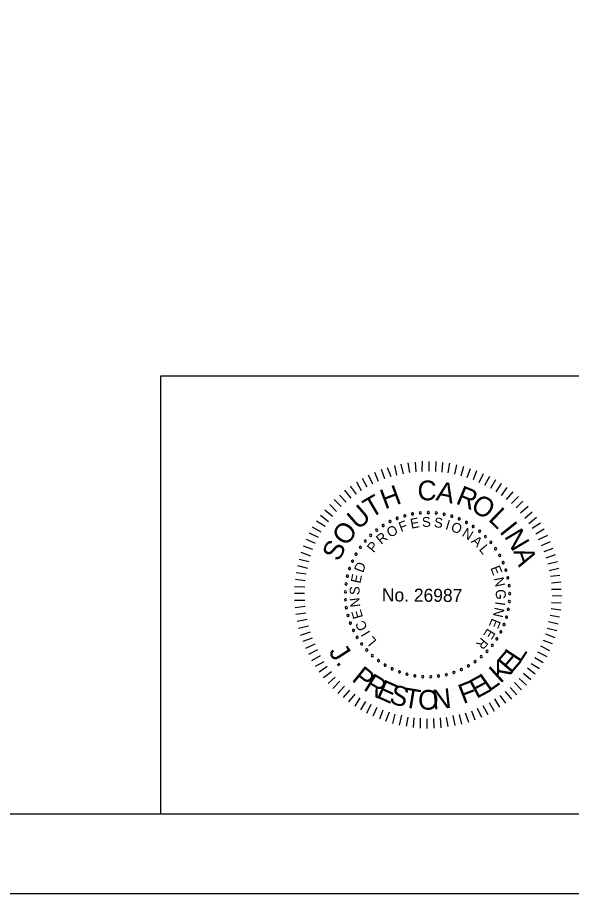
# Model space of a CAD drawing. Extents: x -125.5 to -89.4, y -5.1 to 16.9.
# Drawn here: x -103.8 to -100.32, y -5.07 to 0.43 of the extents above; entities that cross this region are included whole.
import ezdxf

# ---------------------------------------------------------------- set-up
doc = ezdxf.new("R2010")
doc.units = 0
for name, color, linetype in [('BR_BORDER LINES', 7, 'Continuous'), ('BR_TEXT', 7, 'Continuous'), ('Level 31', 7, 'Continuous')]:
    doc.layers.add(name, color=color, linetype=linetype)

msp = doc.modelspace()

# ---------------------------------------------------------------- linework, layer by layer
at = {"layer": 'BR_BORDER LINES'}
for p, q in [((-102.8989, -1.8161), (-97.5337, -1.8161)), ((-102.8989, -4.5661), (-102.8989, -1.8161)), ((-123.6994, -4.5662), (-90.0334, -4.5662))]:
    msp.add_line(p, q, dxfattribs=at)
at = {"layer": 'BR_TEXT'}
for p, q in [((-101.3372, -2.423), (-101.3461, -2.362)), ((-101.2977, -2.419), (-101.3015, -2.3581)), ((-101.2582, -2.4168), (-101.2576, -2.3524)), ((-101.2161, -2.4146), (-101.2156, -2.3528)), ((-101.1741, -2.4175), (-101.1718, -2.3531)), ((-101.1338, -2.4204), (-101.129, -2.3595)), ((-101.0952, -2.425), (-101.0844, -2.3642)), ((-101.4937, -2.4629), (-101.5147, -2.4044)), ((-101.4541, -2.4504), (-101.476, -2.3927)), ((-101.418, -2.4404), (-101.4312, -2.3793)), ((-101.3767, -2.4304), (-101.3908, -2.3711)), ((-101.0549, -2.4331), (-101.0407, -2.374)), ((-101.0138, -2.4437), (-100.9979, -2.3829)), ((-100.977, -2.4543), (-100.9551, -2.397)), ((-100.9376, -2.4675), (-100.9157, -2.4093)), ((-101.604, -2.5144), (-101.6344, -2.46)), ((-101.5695, -2.4966), (-101.5957, -2.4406)), ((-101.5325, -2.4798), (-101.556, -2.4238)), ((-100.9017, -2.485), (-100.8738, -2.4294)), ((-100.8658, -2.5024), (-100.8345, -2.4469)), ((-100.8282, -2.5208), (-100.796, -2.467)), ((-101.6704, -2.5593), (-101.7095, -2.5083)), ((-101.6394, -2.5381), (-101.6698, -2.4838)), ((-100.795, -2.5451), (-100.761, -2.4913)), ((-100.7617, -2.5668), (-100.7252, -2.5165)), ((-101.7369, -2.6094), (-101.7786, -2.5644)), ((-101.7041, -2.5847), (-101.744, -2.5346)), ((-100.7293, -2.5928), (-100.6886, -2.5434)), ((-100.6977, -2.618), (-100.6545, -2.5737)), ((-101.7958, -2.6673), (-101.8392, -2.6248)), ((-101.7663, -2.6366), (-101.8106, -2.5925)), ((-100.6697, -2.6456), (-100.6264, -2.6022)), ((-100.6416, -2.6768), (-100.594, -2.6351)), ((-101.8469, -2.732), (-101.8964, -2.6922)), ((-101.8209, -2.6988), (-101.8704, -2.6598)), ((-100.6144, -2.7088), (-100.5677, -2.6705)), ((-101.8686, -2.761), (-101.9224, -2.728)), ((-100.5906, -2.7424), (-100.5414, -2.7033)), ((-100.5686, -2.7718), (-100.516, -2.7396)), ((-101.9104, -2.8319), (-101.9668, -2.804)), ((-101.893, -2.7977), (-101.9467, -2.7656)), ((-100.5466, -2.8089), (-100.4931, -2.7776)), ((-101.9279, -2.8687), (-101.9852, -2.8433)), ((-100.5288, -2.8433), (-100.4711, -2.8164)), ((-100.5111, -2.8804), (-100.4543, -2.856)), ((-101.9454, -2.9072), (-102.0035, -2.8852)), ((-100.4943, -2.9192), (-100.4374, -2.8982)), ((-101.97, -2.9833), (-102.0308, -2.9682)), ((-101.9577, -2.9474), (-102.0193, -2.9246)), ((-100.4809, -2.9596), (-100.4232, -2.9378)), ((-101.9772, -3.0253), (-102.0397, -3.0094)), ((-100.4708, -2.9957), (-100.4107, -2.9816)), ((-100.4626, -3.0378), (-100.4024, -3.0229)), ((-101.9878, -3.0613), (-102.0487, -3.0531)), ((-100.4543, -3.074), (-100.3951, -3.0667)), ((-101.9925, -3.1024), (-102.0542, -3.0951)), ((-100.4478, -3.1152), (-100.3868, -3.1088)), ((-101.9974, -3.183), (-102.06, -3.1825)), ((-101.9954, -3.1419), (-102.0597, -3.1414)), ((-100.4464, -3.1547), (-100.3863, -3.1552)), ((-101.9961, -3.226), (-102.0604, -3.2272)), ((-100.4471, -3.2388), (-100.3871, -3.241)), ((-100.4442, -3.1959), (-100.3833, -3.1964)), ((-101.9938, -3.2646), (-102.0556, -3.2718)), ((-100.4492, -3.2774), (-100.3883, -3.2856)), ((-101.9898, -3.3058), (-102.0509, -3.3148)), ((-101.9799, -3.3454), (-102.0426, -3.3586)), ((-100.4564, -3.3185), (-100.3972, -3.3284)), ((-101.9733, -3.3875), (-102.0344, -3.4016)), ((-100.4742, -3.3999), (-100.4143, -3.415)), ((-100.4653, -3.3579), (-100.4053, -3.3721)), ((-101.9616, -3.4245), (-102.0236, -3.4454)), ((-101.95, -3.4632), (-102.0085, -3.4842)), ((-100.4848, -3.4367), (-100.4275, -3.4586)), ((-101.9331, -3.5003), (-101.9908, -3.5272)), ((-100.5163, -3.512), (-100.4599, -3.5399)), ((-100.4989, -3.4752), (-100.4424, -3.4971)), ((-101.9162, -3.5364), (-101.9731, -3.566)), ((-101.8994, -3.5735), (-101.9537, -3.6048)), ((-100.5346, -3.5479), (-100.4774, -3.5784)), ((-101.8756, -3.6106), (-101.93, -3.6419)), ((-100.5756, -3.6213), (-100.5235, -3.6535)), ((-100.553, -3.5846), (-100.5, -3.6168)), ((-101.8544, -3.6399), (-101.9045, -3.6764)), ((-101.829, -3.6736), (-101.8791, -3.7127)), ((-100.6224, -3.6836), (-100.5764, -3.7234)), ((-100.5981, -3.6503), (-100.5495, -3.6876)), ((-101.8043, -3.7073), (-101.8485, -3.7481)), ((-101.7754, -3.7333), (-101.8204, -3.7784)), ((-100.6502, -3.7168), (-100.6033, -3.7584)), ((-101.7465, -3.7636), (-101.7889, -3.8095)), ((-101.714, -3.7895), (-101.7548, -3.8364)), ((-100.7073, -3.7721), (-100.6648, -3.8188)), ((-100.6787, -3.7423), (-100.6362, -3.7882)), ((-101.6808, -3.8156), (-101.7207, -3.8633)), ((-101.6501, -3.8373), (-101.6814, -3.8894)), ((-100.8057, -3.8443), (-100.7727, -3.8969)), ((-100.772, -3.8231), (-100.7364, -3.8714)), ((-100.7392, -3.7976), (-100.6993, -3.8452)), ((-101.6151, -3.8599), (-101.6464, -3.9137)), ((-101.5809, -3.8799), (-101.608, -3.9355)), ((-101.5442, -3.8974), (-101.5687, -3.953)), ((-100.9135, -3.9026), (-100.8865, -3.9586)), ((-100.8773, -3.8857), (-100.8468, -3.9418)), ((-100.8393, -3.8663), (-100.808, -3.9206)), ((-101.5057, -3.9149), (-101.5276, -3.9713)), ((-101.4663, -3.9272), (-101.4891, -3.9854)), ((-101.4304, -3.9395), (-101.4446, -3.9986)), ((-101.3892, -3.9467), (-101.4044, -4.0084)), ((-101.3499, -3.9582), (-101.3598, -4.0165)), ((-101.0675, -3.9494), (-101.0542, -4.0113)), ((-101.0262, -3.9429), (-101.0112, -4.0022)), ((-100.9892, -3.9311), (-100.9682, -3.9897)), ((-100.9496, -3.9194), (-100.9286, -3.9763)), ((-101.3104, -3.9628), (-101.3152, -4.0246)), ((-101.271, -3.9657), (-101.2715, -4.0275)), ((-101.229, -3.9686), (-101.2295, -4.0296)), ((-101.1869, -3.9664), (-101.1857, -4.0282)), ((-101.1466, -3.9642), (-101.1428, -4.026)), ((-101.1079, -3.9602), (-101.098, -4.0186))]:
    msp.add_line(p, q, dxfattribs=at)
for centre, start, end in [((-101.3681, -2.6945), 16.1422, 196.1422), ((-101.3681, -2.6945), 196.1422, 16.1422), ((-101.3196, -2.6831), 10.6038, 190.6038), ((-101.3196, -2.6831), 190.6038, 10.6038), ((-101.2702, -2.6764), 5.0653, 185.0653), ((-101.2702, -2.6764), 185.0653, 5.0653), ((-101.2204, -2.6745), 359.5268, 179.5268), ((-101.2204, -2.6745), 179.5268, 359.5268), ((-101.1707, -2.6774), 173.9884, 353.9884), ((-101.1707, -2.6774), 353.9884, 173.9884), ((-101.1214, -2.6851), 168.4499, 348.4499), ((-101.1214, -2.6851), 348.4499, 168.4499), ((-101.0732, -2.6976), 342.9114, 162.9114), ((-101.5039, -2.7559), 32.7576, 212.7576), ((-101.4607, -2.7311), 27.2191, 207.2191), ((-101.4607, -2.7311), 207.2191, 27.2191), ((-101.4153, -2.7106), 21.6807, 201.6807), ((-101.4153, -2.7106), 201.6807, 21.6807), ((-101.0732, -2.6976), 162.9114, 342.9114), ((-101.0263, -2.7146), 157.373, 337.373), ((-101.0263, -2.7146), 337.373, 157.373), ((-100.9814, -2.736), 151.8345, 331.8345), ((-100.9814, -2.736), 331.8345, 151.8345), ((-101.5445, -2.7848), 38.2961, 218.2961), ((-101.5445, -2.7848), 218.2961, 38.2961), ((-101.5039, -2.7559), 212.7576, 32.7576), ((-100.9387, -2.7617), 146.2961, 326.2961), ((-100.9387, -2.7617), 326.2961, 146.2961), ((-100.8987, -2.7914), 140.7576, 320.7576), ((-100.8987, -2.7914), 320.7576, 140.7576), ((-101.6164, -2.8536), 49.373, 229.373), ((-101.6164, -2.8536), 229.373, 49.373), ((-101.5821, -2.8175), 43.8345, 223.8345), ((-101.5821, -2.8175), 223.8345, 43.8345), ((-100.8617, -2.8249), 135.2191, 315.2191), ((-100.8617, -2.8249), 315.2191, 135.2191), ((-100.8282, -2.8617), 129.6807, 309.6807), ((-100.8282, -2.8617), 309.6807, 129.6807), ((-101.6471, -2.8929), 54.9114, 234.9114), ((-101.6471, -2.8929), 234.9114, 54.9114), ((-100.7983, -2.9016), 124.1422, 304.1422), ((-100.7983, -2.9016), 304.1422, 124.1422), ((-101.6738, -2.935), 60.4499, 240.4499), ((-101.6738, -2.935), 240.4499, 60.4499), ((-100.7724, -2.9442), 118.6038, 298.6038), ((-100.7724, -2.9442), 298.6038, 118.6038), ((-101.7145, -3.0258), 71.5268, 251.5268), ((-101.7145, -3.0258), 251.5268, 71.5268), ((-101.6964, -2.9794), 65.9884, 245.9884), ((-101.6964, -2.9794), 245.9884, 65.9884), ((-100.7508, -2.9891), 113.0653, 293.0653), ((-100.7508, -2.9891), 293.0653, 113.0653), ((-101.7281, -3.0738), 77.0653, 257.0653), ((-101.7281, -3.0738), 257.0653, 77.0653), ((-100.7336, -3.0359), 107.5268, 287.5268), ((-100.7336, -3.0359), 287.5268, 107.5268), ((-100.721, -3.0841), 101.9884, 281.9884), ((-100.721, -3.0841), 281.9884, 101.9884), ((-101.737, -3.1228), 82.6038, 262.6038), ((-101.737, -3.1228), 262.6038, 82.6038), ((-100.7131, -3.1333), 96.4499, 276.4499), ((-100.7131, -3.1333), 276.4499, 96.4499), ((-101.7411, -3.1724), 88.1422, 268.1422), ((-101.7411, -3.1724), 268.1422, 88.1422), ((-100.71, -3.183), 90.9114, 270.9114), ((-100.71, -3.183), 270.9114, 90.9114), ((-101.7404, -3.2223), 93.6807, 273.6807), ((-101.7404, -3.2223), 273.6807, 93.6807), ((-100.7118, -3.2328), 85.373, 265.373), ((-100.7118, -3.2328), 265.373, 85.373), ((-101.7349, -3.2718), 99.2191, 279.2191), ((-101.7349, -3.2718), 279.2191, 99.2191), ((-100.7183, -3.2822), 79.8345, 259.8345), ((-100.7183, -3.2822), 259.8345, 79.8345), ((-101.7246, -3.3206), 104.7576, 284.7576), ((-101.7246, -3.3206), 284.7576, 104.7576), ((-100.7295, -3.3308), 74.2961, 254.2961), ((-100.7295, -3.3308), 254.2961, 74.2961), ((-101.7097, -3.3681), 110.2961, 290.2961), ((-101.7097, -3.3681), 290.2961, 110.2961), ((-101.6903, -3.414), 115.8345, 295.8345), ((-101.6903, -3.414), 295.8345, 115.8345), ((-100.7454, -3.378), 68.7576, 248.7576), ((-100.7454, -3.378), 248.7576, 68.7576), ((-101.6665, -3.4578), 121.373, 301.373), ((-101.6665, -3.4578), 301.373, 121.373), ((-100.7904, -3.4668), 57.6807, 237.6807), ((-100.7904, -3.4668), 237.6807, 57.6807), ((-100.7658, -3.4235), 63.2191, 243.2191), ((-100.7658, -3.4235), 243.2191, 63.2191), ((-101.6386, -3.4991), 126.9114, 306.9114), ((-101.6386, -3.4991), 306.9114, 126.9114), ((-100.8192, -3.5075), 52.1422, 232.1422), ((-100.8192, -3.5075), 232.1422, 52.1422), ((-101.6069, -3.5375), 132.4499, 312.4499), ((-101.6069, -3.5375), 312.4499, 132.4499), ((-101.5716, -3.5727), 137.9884, 317.9884), ((-101.5716, -3.5727), 317.9884, 137.9884), ((-100.8877, -3.5797), 41.0653, 221.0653), ((-100.8517, -3.5452), 46.6038, 226.6038), ((-100.8517, -3.5452), 226.6038, 46.6038), ((-101.5331, -3.6043), 143.5268, 323.5268), ((-101.5331, -3.6043), 323.5268, 143.5268), ((-101.4917, -3.632), 149.0653, 329.0653), ((-101.4917, -3.632), 329.0653, 149.0653), ((-100.9269, -3.6105), 35.5268, 215.5268), ((-100.9269, -3.6105), 215.5268, 35.5268), ((-100.8877, -3.5797), 221.0653, 41.0653), ((-101.4478, -3.6556), 154.6038, 334.6038), ((-101.4478, -3.6556), 334.6038, 154.6038), ((-101.4018, -3.6749), 160.1422, 340.1422), ((-101.4018, -3.6749), 340.1422, 160.1422), ((-101.3542, -3.6896), 345.6807, 165.6807), ((-101.0595, -3.6784), 18.9114, 198.9114), ((-101.0595, -3.6784), 198.9114, 18.9114), ((-101.0132, -3.6601), 24.4499, 204.4499), ((-101.0132, -3.6601), 204.4499, 24.4499), ((-100.9688, -3.6374), 29.9884, 209.9884), ((-100.9688, -3.6374), 209.9884, 29.9884), ((-101.3542, -3.6896), 165.6807, 345.6807), ((-101.3054, -3.6997), 351.2191, 171.2191), ((-101.3054, -3.6997), 171.2191, 351.2191), ((-101.2559, -3.705), 356.7576, 176.7576), ((-101.2559, -3.705), 176.7576, 356.7576), ((-101.2061, -3.7055), 2.2961, 182.2961), ((-101.2061, -3.7055), 182.2961, 2.2961), ((-101.1564, -3.7012), 7.8345, 187.8345), ((-101.1564, -3.7012), 187.8345, 7.8345), ((-101.1074, -3.6921), 13.373, 193.373), ((-101.1074, -3.6921), 193.373, 13.373)]:
    msp.add_arc(centre, 0.00701, start, end, dxfattribs=at)
at = {"layer": 'Level 31'}
msp.add_lwpolyline([(-125.5328, 16.9339), (-125.5328, -5.0661), (-89.5328, -5.0661), (-89.5328, 16.9339)], dxfattribs=at)

# ---------------------------------------------------------------- texts
at = {"layer": 'BR_TEXT'}
for s, height, rotation, p in [('C', 0.1241, 359.5482, (-101.2889, -2.5969)), ('H', 0.1241, 20.3637, (-101.4933, -2.6552)), ('A', 0.1241, 348.1981, (-101.1775, -2.5961)), ('R', 0.1241, 337.4344, (-101.0542, -2.616)), ('T', 0.1241, 30.4992, (-101.5812, -2.7128)), ('O', 0.1239, 326.5869, (-100.962, -2.6528)), ('U', 0.1241, 40.8022, (-101.6624, -2.7875)), ('L', 0.1241, 315.9488, (-100.8494, -2.7205)), ('O', 0.1241, 52.0267, (-101.7369, -2.8914)), ('F', 0.0622, 20.6127, (-101.392, -2.7981)), ('E', 0.0622, 11.4103, (-101.3269, -2.7764)), ('S', 0.0622, 2.208, (-101.2591, -2.7654)), ('S', 0.0622, 352.6608, (-101.1878, -2.7657)), ('I', 0.0622, 343.1136, (-101.1175, -2.7777)), ('O', 0.0622, 338.4392, (-101.0841, -2.7878)), ('I', 0.1241, 308.6613, (-100.778, -2.7948)), ('R', 0.0622, 40.3949, (-101.5156, -2.878)), ('O', 0.0622, 30.8477, (-101.4594, -2.8341)), ('N', 0.0622, 328.2042, (-101.0145, -2.8192)), ('N', 0.1241, 300.7037, (-100.7474, -2.8242)), ('S', 0.1239, 63.2511, (-101.7823, -2.9871)), ('P', 0.0622, 49.9421, (-101.5636, -2.9306)), ('A', 0.0622, 318.657, (-100.9555, -2.8592)), ('L', 0.0622, 309.4546, (-100.9057, -2.9066)), ('A', 0.1241, 289.4792, (-100.6882, -2.9172)), ('D', 0.0622, 69.0364, (-101.6306, -3.0559)), ('E', 0.0622, 291.049, (-100.8319, -3.0219)), ('E', 0.0622, 78.2388, (-101.6472, -3.1226)), ('N', 0.0622, 281.8466, (-100.8097, -3.0869)), ('S', 0.0622, 87.786, (-101.6529, -3.1936)), ('No. 26987', 0.08175, 359.5268, (-101.5118, -3.232)), ('G', 0.0622, 272.2995, (-100.7979, -3.1572)), ('N', 0.0622, 97.3332, (-101.6467, -3.2646)), ('I', 0.0622, 262.4084, (-100.7983, -3.231)), ('E', 0.0622, 106.5355, (-101.6297, -3.3312)), ('N', 0.0622, 257.7339, (-100.8028, -3.2656)), ('C', 0.0622, 116.4266, (-101.5998, -3.3987)), ('E', 0.0622, 248.1867, (-100.8209, -3.3346)), ('E', 0.0622, 238.9844, (-100.8488, -3.3973)), ('I', 0.0622, 121.1011, (-101.5818, -3.4285)), ('L', 0.0622, 129.9595, (-101.5411, -3.4807)), ('R', 0.0622, 229.782, (-100.8865, -3.4548)), ('J', 0.1236, 302.9559, (-101.849, -3.5492)), ('E', 0.1236, 49.3639, (-100.703, -3.6911)), ('L', 0.1236, 56.4247, (-100.6455, -3.6233)), ('.', 0.1236, 309.3974, (-101.8049, -3.6172)), ('K', 0.1236, 42.3031, (-100.7683, -3.7512)), ('P', 0.1236, 321.1035, (-101.7065, -3.7264)), ('R', 0.1236, 328.5359, (-101.6332, -3.7844)), ('E', 0.1236, 335.9684, (-101.5531, -3.8325)), ('F', 0.1236, 21.1206, (-101.0013, -3.8776)), ('E', 0.1236, 28.1814, (-100.9186, -3.8452)), ('L', 0.1236, 35.2422, (-100.8406, -3.8028)), ('S', 0.1236, 343.0292, (-101.4718, -3.8682)), ('T', 0.1236, 350.4617, (-101.3821, -3.8947)), ('O', 0.1236, 358.1419, (-101.2867, -3.9097)), ('N', 0.1236, 5.8221, (-101.1902, -3.9118))]:
    msp.add_text(s, height=height, rotation=rotation, dxfattribs=at).set_placement(p)

doc.saveas('drawing.dxf')
